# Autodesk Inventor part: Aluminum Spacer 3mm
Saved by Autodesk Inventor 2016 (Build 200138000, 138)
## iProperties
Created: 2015-11
Part Number: Aluminum Spacer 3mm
Material: Generic
Document SubType Name: Modeling
Designer: John
Density: 1 g/cm^3
Appearance: Default
Author: John
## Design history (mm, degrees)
feature "SOLID1"
body "Solid1"
